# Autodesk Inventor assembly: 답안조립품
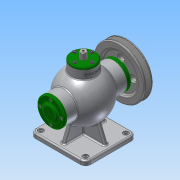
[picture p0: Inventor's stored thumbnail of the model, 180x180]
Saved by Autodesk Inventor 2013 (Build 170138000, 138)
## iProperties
Created: 2018-06
Part Number: 답안조립품
Document SubType Name: Assembly
Designer: Administrator
Author: Administrator
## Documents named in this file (19)
- C:\Users\Administrator\Desktop\480612V1015\답안조립품.iam
- C:\Users\Administrator\Desktop\480612V1015\본체.ipt
- C:\Users\Administrator\Desktop\480612V1015\V-벨트풀리.ipt
- C:\Users\Administrator\Desktop\480612V1015\너트 M8.ipt
- C:\Users\Administrator\Desktop\480612V1015\뒤커버.ipt
- C:\Users\Administrator\Desktop\480612V1015\멈춤링 15x1.ipt
- C:\Users\Administrator\Desktop\480612V1015\멈춤링 35x1.6.ipt
- 멈춤링 35x1.6.ipt
- C:\Users\Administrator\Desktop\480612V1015\베어링 6202.ipt
- 베어링 6202.ipt
- C:\Users\Administrator\Desktop\480612V1015\볼트 M4x12.ipt
- C:\Users\Administrator\Desktop\480612V1015\볼트 M4x16.ipt
- C:\Users\Administrator\Desktop\480612V1015\부시.ipt
- C:\Users\Administrator\Desktop\480612V1015\상부커버.ipt
- C:\Users\Administrator\Desktop\480612V1015\슬라이드.ipt
- C:\Users\Administrator\Desktop\480612V1015\앞커버.ipt
- C:\Users\Administrator\Desktop\480612V1015\오일 실 15 30 7.ipt
- C:\Users\Administrator\Desktop\480612V1015\키 4x4x12.ipt
- C:\Users\Administrator\Desktop\480612V1015\편심축.ipt
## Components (1 placed, 1 different names)
1. V-벨트풀리:1 — 각도:1
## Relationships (1: Angle 1)
- 각도:1 [Angle]: V-벨트풀리:1
